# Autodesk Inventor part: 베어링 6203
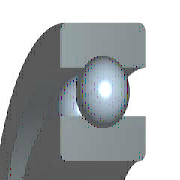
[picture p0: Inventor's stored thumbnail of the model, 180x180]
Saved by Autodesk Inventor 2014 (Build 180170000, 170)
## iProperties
IsCustomPart: 1
Created: 2015-09
Part Number: 베어링 6203
Material: 강철, 연강
Description: 깊은 그루브 볼 베어링
Document SubType Name: Modeling
Standard: KS B 2023
Standards Organization: KS
Language: ko-KR
Size Designation: 6203 - 17 x 40 x 12
Categories: <MemberInstance><Categories><Category DisplayName="샤프트 부품" InternalName="7f7aeb1f-a693-4053-b835-cee3144e0d98" Mnemonic="SHFT"><Category DisplayName="베어링" Inter
Density: 1 g/cm^3
Appearance: 강철
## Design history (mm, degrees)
sketch "스케치" dims "d0" = 5.98 (= -0.26 x WD + 0.26 x BD)
  geometry: L1 (3.01, 14.25)-(8.99, 14.25); L2 (6, 14.25)-(6, 11.26); L3 (6, 14.25)-(6, 17.24); L4 (3.778, 12.249)-(0, 12.249); L5 (0, 8.5)-(12, 8.5); L6 (3.778, 16.251)-(0, 16.251); L7 (0, 20)-(12, 20); L8 (12, 8.5)-(12, 12.249); L9 (8.222, 12.249)-(12, 12.249); L10 (8.222, 16.251)-(12, 16.251); L11 (12, 20)-(12, 16.251); L12 (-1.4, 0)-(8.4, 0) reference; L13 (0, -0.3)-(0, 5.3) reference
  constraints: 22 end point, 4 point on line, 2 collinear, 2 perpendicular, 2 symmetric about line, 1 midpoint, 1 parallel, 14 other
  dimensions: "d9" = 17 diameter of L5 L12 (= WD); "d11" = 40 diameter of L7 L12 (= BD); "d12" = 12 distance between parallel lines of L8 L13 (= KB); "d13" = 24.498 diameter of L9 L12 (= 0.326 x BD + 0.674 x WD)
revolve "본체" stored, may be unused: angle "d6" = 90 deg
revolve "볼" stored, may be unused: angle "d7" = 90 deg
pattern_circular "IDS_ARRAYBALL[SIMPL:T]" dims angle "d3" = 360 deg
body "Solid1"
fillet "모깎기1" dims "d1" = 0.6 (= KRS)
other parameters: "WD" = 17 [user parameter; used in 5 equation terms], "BD" = 40 [user parameter; used in 5 equation terms], "KB" = 12 [user parameter; used in 1 equation term], "KRS" = 0.6 [user parameter; used in 1 equation term], "d4" = 0, "d5" = 0, "d8" = 0, "d14" = 0, "d15" = 0, "BBA" = 0 [user parameter], "BC0" = 4750000 [user parameter], "BC" = 9560000 [user parameter], "WR" = 8.5 (= 0.5 x WD) [user parameter]
